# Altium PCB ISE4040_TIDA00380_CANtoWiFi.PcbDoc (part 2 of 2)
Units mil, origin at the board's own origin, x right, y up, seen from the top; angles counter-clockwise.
Board outline 2700 x 3450 mil, 4 copper layers (Top Layer, Signal Layer 1, Signal Layer 2, Bottom Layer), stack 61.6 mil thick; 119 components, 58 nets, 367 pads, 332 vias.
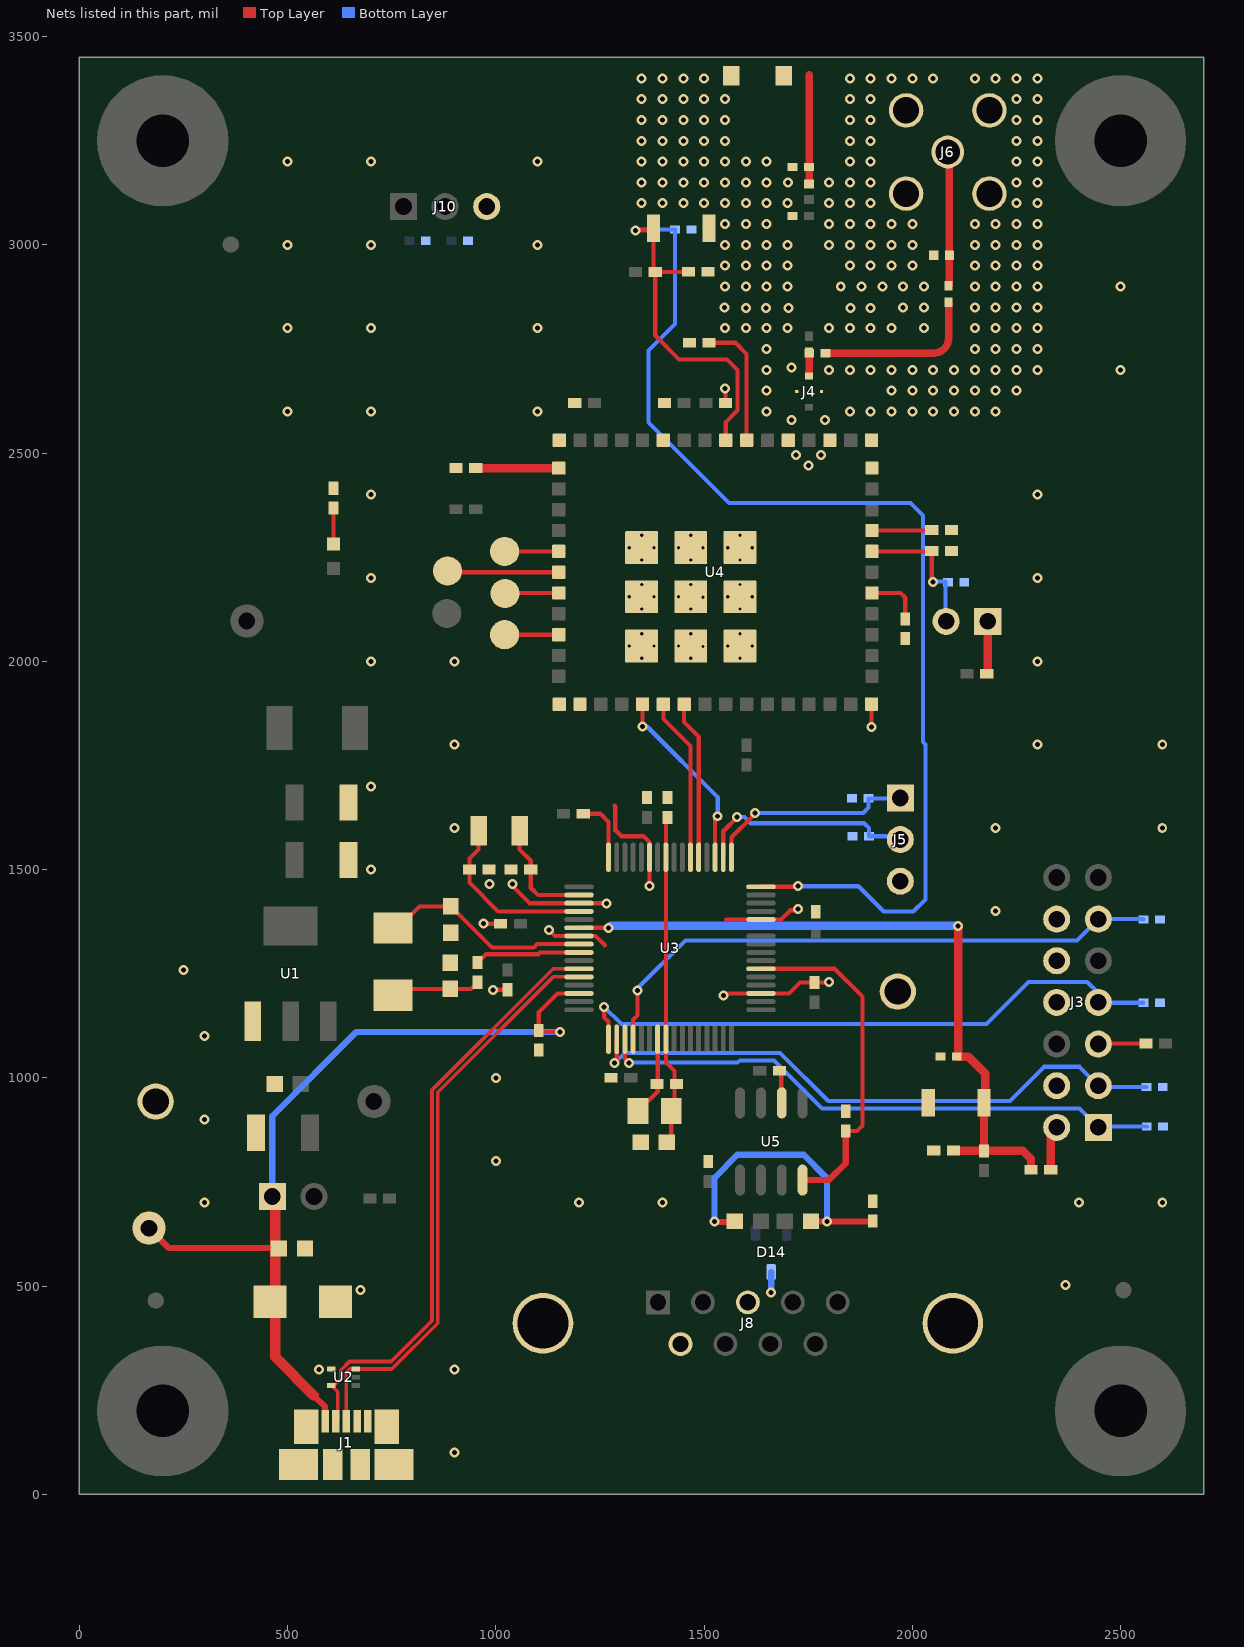
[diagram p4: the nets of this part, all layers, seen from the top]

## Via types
v1: diameter 24, hole 12, Top Layer to Bottom Layer, tented both sides, 294 vias
v2: diameter 19.68, hole 7.87, Top Layer to Bottom Layer, tented both sides, 36 vias
v3: diameter 34, hole 16, Top Layer to Bottom Layer, tented both sides, 2 vias

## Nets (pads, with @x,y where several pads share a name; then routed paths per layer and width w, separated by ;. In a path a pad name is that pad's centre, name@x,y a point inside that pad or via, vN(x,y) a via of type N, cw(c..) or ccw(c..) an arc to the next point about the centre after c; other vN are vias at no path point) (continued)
GND: C1.2 C2.2 C3.2 C4.2 C5.2 C6.2 C7.2 C8.2 C9.2 C10.2 C11.2 C12.2 C13.2 C14.2 C15.2 C18.1 C18.2 C19.2 C20.2 C21.1 C22.1 C23.2 C33.2 C34.2 C35.2 C36.2 C38.2 C39.2 C40.2 C41.2 C42.2 D1.2 D4.2 D6.2 D7.2 D8.2 D9.2 D10.2 D11.2 D12.2 D13.2 D14.3 D15.2 D16.2 E1.1 E1.2 J1.5 J1.6 J1.7 J1.8 J1.9 J1.10 J1.11 J3.4 J3.8 J3.10 J3.12 J4.3 J4.4 J5.3 J6.2 J6.3 J6.4 J6.5 J8.3 J8.6 J8.10 J8.11 J10.3 L3.1 L4.2 R21.1 R23.1 R25.1 R26.1 R27.1 R29.1 R30.1 S1.2 S2.2 TP4.1 TP5.1 U1.1 U2.4 U3.3 U3.12 U3.27 U3.35 U3.39 U3.55 U4.1 U4.2 U4.16 U4.27 U4.28 U4.30 U4.32 U4.38 U4.43 U4.55 U4.56 U4.57 U4.58 U4.59 U4.60 U4.61 U4.62 U4.63 U5.2 | length 1856.2
  Top Layer w10: U2.4@604.47,300.68 U2.4@605.68,300.68 ; v1(970,1370) C6.2@1011.38,1370 ; v1(993,1211) 993.38,1211.38 C7.2@1028,1211.38 ; v1(1040,1465) 1040,1460.22 1080.95,1419.27 U3.35@1199.5,1419.27 v1@1265.73,1419.27 ; v1(1127,1355) 1141.47,1340.53 U3.39@1199.5,1340.53 1239.11,1340.53 1261.43,1318.21 ; 1284.63,1653.53 1286.72,1651.44 1286.72,1594.33 1300.88,1580.17 1354.52,1580.17 1368.79,1565.9 U3.27@1368.79,1529.5 v1@1368.79,1461.21 ; C14.2@1341,920 1388.47,967.47 U3.55@1388.47,1092.5 ; v1(1547,1198) 1551.73,1202.73 U3.3@1636.5,1202.73 1704,1202.73 1729.89,1228.62 C9.2@1765,1228.62 1798.62,1228.62 v1(1800,1230) ; v1(1550,2655) 1551.62,2653.38 C39.2@1551.62,2620 ; 1553.22,1380.42 1553.74,1379.9 U3.12@1636.5,1379.9 1684.95,1379.9 1707.34,1402.29 1725,1402.29 v1(1725,1405) ; C35.2@1680.62,1017 1685,1012.62 1685,940.87 U5.2@1686.35,939.52 ; v1(1902,1842) U4.16@1902,1897.07
  Top Layer w18: L4.2@1752,3146 1752,3408
  Bottom Layer w15: v1@1661,486 D14.3@1661,533.76
  other v1: 900,100 575,300 900,300 1660,485 675,490 2368,502.12 300,700 1200,700 1400,700 2400,700 2600,700 1000,800 300,900 1000,1000 300,1100 249.3,1258.8 2200,1400 1265,1419 1368.79,1460.21 985,1465 700,1500 900,1600 2200,1600 2600,1600 700,1700 900,1800 2300,1800 2600,1800 700,2000 900,2000 2300,2000 700,2200 2300,2200 700,2400 2300,2400 1750,2470 1720,2495 1780,2495 1710,2580 1790,2580 500,2600 700,2600 1100,2600 1650,2600 1850,2600 1900,2600 1950,2600 2000,2600 2050,2600 2100,2600 2150,2600 2200,2600 1650,2650 1950,2650 2000,2650 2050,2650 2100,2650 2150,2650 2200,2650 2250,2650 1650,2700 1800,2700 1850,2700 1900,2700 1950,2700 2000,2700 2050,2700 2100,2700 2150,2700 2200,2700 2250,2700 2300,2700 2500,2700 1710,2705 1650,2750 2150,2750 2200,2750 2250,2750 2300,2750 500,2800 700,2800 1100,2800 1550,2800 1600,2800 1650,2800 1700,2800 1800,2800 1850,2800 1900,2800 1950,2800 2028,2800 2150,2800 2200,2800 2250,2800 2300,2800 1702,2848 1600,2849 1649,2849 1851,2849 1900,2849 1549,2850 1978,2850 2028,2850 2150,2850 2200,2850 2250,2850 2300,2850 1550,2900 1600,2900 1650,2900 1700,2900 1828,2900 1878,2900 1928,2900 1978,2900 2028,2900 2150,2900 2200,2900 2250,2900 2300,2900 2500,2900 1550,2950 1600,2950 1650,2950 1700,2950 1850,2950 1900,2950 1950,2950 2000,2950 2150,2950 2200,2950 2250,2950 2300,2950 500,3000 700,3000 1100,3000 1550,3000 1600,3000 1650,3000 1700,3000 1800,3000 1850,3000 1900,3000 1950,3000 2000,3000 2150,3000 2200,3000 2250,3000 2300,3000 1550,3050 1600,3050 1650,3050 1800,3050 1850,3050 1900,3050 1950,3050 2000,3050 2150,3050 2200,3050 2250,3050 2300,3050 1350,3100 1400,3100 1450,3100 1500,3100 1550,3100 1600,3100 1650,3100 1700,3100 1800,3100 1850,3100 1900,3100 2250,3100 2300,3100 1350,3150 1400,3150 1450,3150 1500,3150 1550,3150 1600,3150 1650,3150 1701,3150 1800,3150 1850,3150 1900,3150 2250,3150 2300,3150 500,3200 700,3200 1100,3200 1350,3200 1400,3200 1450,3200 1500,3200 1550,3200 1600,3200 1650,3200 1850,3200 1900,3200 2250,3200 2300,3200 1350,3250 1400,3250 1450,3250 1500,3250 1550,3250 1850,3250 1900,3250 2250,3250 2300,3250 1350,3300 1400,3300 1450,3300 1500,3300 1550,3300 1850,3300 1900,3300 2250,3300 2300,3300 1350,3350 1400,3350 1450,3350 1500,3350 1550,3350 1850,3350 1900,3350 2250,3350 2300,3350 1350,3400 1400,3400 1450,3400 1500,3400 1850,3400 1900,3400 1950,3400 2000,3400 2050,3400 2150,3400 2200,3400 2250,3400 2300,3400
  other v2: 1349.83,2007.31 1467.94,2007.31 1586.06,2007.31 1497.47,2035.85 1320.31,2036.83 1379.36,2036.83 1438.42,2036.83 1556.53,2036.83 1615.58,2036.83 1349.83,2066.36 1467.94,2066.36 1586.06,2066.36 1349.83,2125.42 1467.94,2125.42 1586.06,2125.42 1497.47,2153.96 1320.31,2154.94 1379.36,2154.94 1438.42,2154.94 1556.53,2154.94 1615.58,2154.94 1349.83,2184.47 1467.94,2184.47 1586.06,2184.47 1349.83,2243.53 1467.94,2243.53 1586.06,2243.53 1320.31,2273.06 1379.36,2273.06 1438.42,2273.06 1497.47,2273.06 1556.53,2273.06 1615.58,2273.06 1349.83,2302.58 1467.94,2302.58 1586.06,2302.58
ID: J1.4
MOSI_CC: U3.22 U4.6 | length 394.6
  Top Layer w10: U4.6@1402,1897.07 1402,1862 1467.21,1796.79 U3.22@1467.21,1529.5
NetC21_2: C21.2 U3.34 Y1.1 | length 270.9
  Top Layer w10: Y1.1@1056.86,1593.15 1056.86,1548.14 1083.62,1521.38 C21.2@1083.62,1500 1083.62,1456.38 1101.05,1438.95 U3.34@1199.5,1438.95
NetC22_2: C22.2 U3.36 Y1.2 | length 425.4
  Top Layer w10: Y1.2@958.44,1593.15 958.44,1548.44 936.38,1526.38 C22.2@936.38,1500 936.38,1468.62 1005.42,1399.58 U3.36@1199.5,1399.58
NetC34_1: C34.1 R17.1 Y2.1 | length 215.9
  Top Layer w10: Y2.1@753,1198.29 768.21,1213.5 C34.1@890,1213.5 940.13,1213.5 R17.1@956,1229.38
NetC41_1: C41.1 R18.1 R19.1 | length 721.5
  Top Layer w15: v1@1526,654 R19.1@1571.5,654 ; R18.1@1754.5,655 v1(1795,655) 1903.62,655 C41.1@1905,656.38
  Bottom Layer w15: v1(1525,655) 1525,760 1580,815 1738.96,815 1795,758.96 v1(1795,655)
NetD5_2: D5.2 R21.2 | length 86.9
  Top Layer w10: D5.2@609.68,2281.53 R21.2@609.68,2368.38
NetJ3_5: J3.5 R14.1 | length 114.8
  Top Layer w10: J3.5@2446.5,1081 2447.5,1082 R14.1@2560.88,1082
NetJ11_1: J11.1 R28.1 | length 127
  Top Layer w20: R28.1@2178.62,1970 2181,1972.38 J11.1@2181,2096
NetR16_2: R16.2 U3.32 | length 153.9
  Top Layer w10: R16.2@1209.62,1634 1251,1634 1270.36,1614.64 U3.32@1270.36,1529.5
NetR30_2: R30.2 U4.21 | length 135.7
  Top Layer w10: U4.21@1902.98,2164 1971.62,2164 1983,2152.62 R30.2@1983,2101.62
NetTP7_1: TP7.1 U4.48 | length 130
  Top Layer w10: TP7.1@1021,2264 U4.48@1151.02,2264
NetTP8_1: TP8.1 U4.49 | length 268.3
  Top Layer w10: TP8.1@884,2217 887,2214 U4.49@1151.02,2214
NetTP9_1: TP9.1 U4.50 | length 128
  Top Layer w10: TP9.1@1023,2164 U4.50@1151.02,2164
NetTP10_1: TP10.1 U4.52 | length 130
  Top Layer w10: TP10.1@1021,2064 U4.52@1151.02,2064
NRST_CC: C42.1 D15.1 R22.1 S2.1 U3.16 U4.35 | length 3490.1
  Top Layer w10: v1(1335,3035) 1373.07,3035 S2.1@1378.07,3040 1378.07,2939.55 R22.1@1382.62,2935 ; C42.1@1462.38,2935.5 1461.88,2935 R22.1@1382.62,2935 ; U4.35@1552,2530.93 1552,2574.61 1580.24,2602.86 1580.24,2699.76 1555,2725 1440,2725 1382.62,2782.38 R22.1@1382.62,2935 ; U3.16@1636.5,1458.64 v1@1723.64,1458.64
  Bottom Layer w10: v1(1335,3035) 1340,3035 1342,3037 D15.1@1430.32,3037 1430.32,2810.31 1366.03,2746.03 1366.03,2573.97 1560,2380 1995.13,2380 2025.13,2350 2025.13,1806.77 2031.53,1800.37 2031.53,1428.37 2002.04,1398.88 1931.28,1398.88 1870.16,1460 v1(1725,1460)
NRST_TM4C: C20.1 D4.1 R11.1 R12.1 S1.1 U3.38 | length 1725.4
  Top Layer w10: U3.38@1199.5,1360.21 v1@1274.79,1360.21
  Top Layer w20: C20.1@2098.62,825 2099,824.62 R11.1@2172,824.62 ; v1(2110,1365) 2110,1054.13 D4.1@2106.68,1050.81 2134.19,1050.81 2175,1010 2175,943.07 S1.1@2171.93,940 2171.93,824.69 R11.1@2172,824.62 ; R12.1@2284.88,779 2284.88,805.12 2265.38,824.62 R11.1@2172,824.62
  Bottom Layer w20: v1(1270,1360) 1275,1365 v1(2110,1365)
NRTS: R23.2 U4.44 | length 199.4
  Top Layer w20: R23.2@951.62,2464 U4.44@1151.02,2464
NTRST: J3.2 R12.2 | length 108
  Top Layer w20: R12.2@2332.13,779 2332.13,866.62 J3.2@2346.5,881
OCS1: R17.2 U3.41 | length 253.7
  Top Layer w10: R17.2@956,1276.62 975.94,1296.56 1101.56,1296.56 1106.16,1301.16 U3.41@1199.5,1301.16
OSC0: C33.1 U3.40 Y2.2 | length 512
  Top Layer w10: Y2.2@753,1359.71 764.71,1359.71 816.5,1411.5 C33.1@892,1411.5 990.5,1313 1091,1313 1098.84,1320.84 U3.40@1199.5,1320.84
RF_FL_O: J4.2 R13.1 R15.2 | length 54.9
  Top Layer w10: R13.1@1752,2739.69 R13.1@1752.32,2740
  Top Layer w18: J4.2@1752,2685.2 R13.1@1752,2739.69
S: R29.2 U3.6 U5.8 | length 824.2
  Top Layer w10: U3.6@1636.5,1261.79 1813.21,1261.79 1880,1195 1880,885 1867.38,872.38 R29.2@1840,872.38
  Top Layer w15: U5.8@1736.35,754.48 1799.48,754.48 1840,795 R29.2@1840,872.38
SCLK_CC: U3.19 U4.5 | length 441.7
  Top Layer w10: v1@1352,1844 U4.5@1352,1897.07 ; U3.19@1526.27,1529.5 v1@1526.27,1621.73
  Bottom Layer w10: v1(1352,1843) 1363.36,1843 1532.54,1673.82 v1(1532.54,1628)
SMA_LEG: C17.2 R13.2 | length 402.2
  Top Layer w18: R13.2@1791.69,2740 2051.17,2740 ccw(c2051.17,2775.83) 2087,2775.83 C17.2@2087,2862.31
SMA_OUT: C17.1 J6.1 L3.2 | length 323.6
  Top Layer w10: J6.1@2085,3223 J6.1@2088.7,3219.3 ; L3.2@2088.7,2975 L3.2@2088.7,2978.3
  Top Layer w18: C17.1@2087,2901.69 2088.7,2903.39 L3.2@2088.7,2975 ; L3.2@2088.7,2978.3 J6.1@2088.7,3219.3
SOMI_CC: U3.21 U4.7 | length 382
  Top Layer w10: U4.7@1452,1897.07 1452,1854 1486.9,1819.1 U3.21@1486.9,1529.5
SOP0: R25.2 U4.34 | length 308.6
  Top Layer w10: R25.2@1511.62,2765 1575,2765 1602,2738 U4.34@1602,2530.93
SOP1: R26.2 U4.24 | length 143.8
  Top Layer w10: U4.24@1902.98,2314 2045.38,2314 R26.2@2046.38,2315
SOP2: D16.1 J11.2 R27.2 U4.23 | length 348.3
  Top Layer w10: U4.23@1902.98,2264 2045.38,2264 R27.2@2046.38,2265 2046.38,2193.62 v1(2050,2190)
  Bottom Layer w10: v1@2048,2192 2079.32,2192 2079.32,2097.68 J11.2@2081,2096
TCK: D13.1 J3.11 U3.52 | length 1411.4
  Top Layer w10: U3.52@1329.42,1092.5 1329.42,1139.42 1340,1150 v1(1340,1210)
  Bottom Layer w10: v1(1340,1210) 1340,1215 1455,1330 2395.51,1330 J3.11@2446.5,1381 2554.32,1381 D13.1@2555.32,1380
TDI: D11.1 J3.3 U3.50 | length 1448.8
  Top Layer w10: v1(1285,1035) 1290.05,1040.05 U3.50@1290.05,1092.5
  Bottom Layer w10: v1(1285,1035) 1285,1035.18 1309.7,1059.87 1682.35,1059.87 1798,944.22 2234.22,944.22 2316.35,1026.35 2401.15,1026.35 J3.3@2446.5,981 2449.5,978 D11.1@2561.82,978
TDO: D10.1 J3.7 U3.49 | length 1465
  Top Layer w10: v1@1260,1165 1260,1145 1270.36,1134.64 U3.49@1270.36,1092.5
  Bottom Layer w10: v1(1260,1170) 1301.23,1128.77 2177.7,1128.77 2278.93,1230 2420,1230 2446.5,1203.5 J3.7@2446.5,1181 2447.5,1180 D10.1@2555.32,1180
TM4C_RX: D7.1 J5.2 U3.18 | length 536.3
  Top Layer w10: U3.18@1545.95,1529.5 1545.95,1591.95 v1@1580,1626
  Bottom Layer w10: v1(1579,1626) 1596.82,1626 1611.7,1611.13 1883.87,1611.13 1895.68,1599.32 D7.1@1895.68,1580 1963,1580 J5.2@1971,1572
TM4C_TX: D6.1 J5.1 U3.17 | length 510.6
  Top Layer w10: U3.17@1565.64,1529.5 1565.64,1577.64 1589.13,1601.13 1589.3,1601.13 1603.87,1615.7 1603.87,1615.87 v1@1626,1638
  Bottom Layer w10: v1(1622,1636) 1882,1636 1894.68,1648.68 D6.1@1894.68,1671 1970,1671 J5.1@1971,1672
TMS: D12.1 J3.1 U3.51 | length 1374.9
  Top Layer w10: U3.51@1309.73,1092.5 1309.73,1045.27 v1(1320,1035)
  Bottom Layer w10: v1(1320,1035) 1321.35,1036.35 1580.17,1036.35 1585.7,1041.87 1667.48,1041.87 1783,926.35 2401.15,926.35 J3.1@2446.5,881 2448.5,883 D12.1@2562.82,883
USB_D_N: J1.2 U2.5 U3.43 | length 1440
  Top Layer w8.5: J1.2@615.41,175.61 620.02,180.22 620.02,245.77 U2.5@604.47,261.31 611.31,261.31 627.5,277.5 627.5,297.84 648.37,318.71 748.71,318.71 846.5,416.5 846.5,970.59 1137.7,1261.79 U3.43@1199.5,1261.79
USB_D_P: J1.3 U2.3 U3.44 | length 1393.2
  Top Layer w8.5: J1.3@641,175.61 641,292.25 649.44,300.68 U2.3@663.53,300.68 749.78,300.68 860,410.91 860,965 1137.1,1242.1 U3.44@1199.5,1242.1
VBUS: C1.1 C23.1 D1.1 J1.1 J2.1 TP1.1 U3.46 | length 2132.1
  Top Layer w10: v1(1154.22,1110) 1099.38,1110 C23.1@1103,1113.62 1103,1158 1147.73,1202.73 U3.46@1199.5,1202.73
  Top Layer w15: TP1.1@167,639 215,591 C1.1@470,591 ; D1.1@457.26,462 D1.1@470,474.74 ; 563,237 589.82,210.18 J1.1@589.82,175.61
  Top Layer w25: J2.1@463,715 J2.1@470,708 ; J2.1@478.5,699.5 J2.1@470,708 ; 563,237 470,330 470,474.74 470,591 J2.1@470,708
  Bottom Layer w15: J2.1@463,715 463,908 665,1110 v1(1154.22,1110)
VDDC_TM4C: C12.1 C13.1 C14.1 C15.1 U3.25 U3.56 | length 798
  Top Layer w10: C15.1@1410.5,845 1421,855.5 C14.1@1421,920 1428.62,927.62 1428.62,1016.38 1408.16,1036.84 U3.56@1408.16,1092.5 U3.25@1408.16,1529.5 1408.16,1621.54 C12.1@1412,1625.38
pads on no net: FID1.1 FID2.1 FID3.1 H1.1 H2.1 H3.1 H4.1 J3.6 J3.9 J3.13 J3.14 J8.1 J8.4 J8.5 J8.8 J8.9 SH-J2.0 SH-J11.0 U2.1 U2.2 U3.1 U3.4 U3.5 U3.7 U3.8 U3.9 U3.10 U3.13 U3.14 U3.15 U3.28 U3.29 U3.30 U3.31 U3.33 U3.45 U3.47 U3.48 U3.53 U3.57 U3.58 U3.61 U3.62 U3.63 U3.64 U4.3 U4.9 U4.12 U4.13 U4.14 U4.15 U4.17 U4.18 U4.19 U4.20 U4.22 U4.25 U4.26 U4.29 U4.33 U4.39 U4.41 U4.42 U4.45 U4.53 U4.54

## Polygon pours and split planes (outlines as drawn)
GND on Signal Layer 1 "Signal Layer 1-No Net" (solid, remove dead copper, pour order 2): 10,3440 10,10 2690,10 2690,3440
GND on Top Layer "Top Layer-No Net" (solid, remove dead copper, pour order 6): 10,3440 10,10 2690,10 2690,3440
GND on Bottom Layer "Bottom Layer-No Net" (solid, remove dead copper, pour order 8): 10,3440 10,10 2690,10 2690,3440
3V3 on Signal Layer 2 "Signal Layer 2-No Net" (solid, remove dead copper, pour order 4): 10,3440 10,10 2690,10 2690,3440

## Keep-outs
Keep-Out Layer:
  lines w10: -5,3450 cw(c0,3450) 0,3455 ; 2600,3455 2700,3455 cw(c2700,3450) 2705,3450 2705,0 cw(c2700,0) 2700,-5 0,-5 cw(c0,0) -5,0 -5,3455 2610,3455
  text ".Layer_Name" at 577,-858.49 h60

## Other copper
Top Layer:
  rectangle net 3V3: 638,1787 782.77,1894
  pour cut-out: 610.8,1913.15 550,1913.15 550,1766 624,1766 624,1899.95
  region net 3V3_OUT: 573,1418 538,1418 538,2161 30,2161 30,1317 573,1317
  pour cut-out: 980,1235 980,1225 1085,1225 1085,1235
  pour cut-out: 1525,1870 1525,1855 1585,1855 1585,1870
  pour cut-out: 1052.87,1473.19 1052.87,1425.79 1085,1425.79 1085,1475 1083.19,1473.19
  pour cut-out: 950,1435 915,1435 915,1473.19 950,1473.19
  pour cut-out: 550,1205 530,1205 530,1195 550,1195
  pour cut-out: 485,1069.8 485,1032.8 501.66,1032.8 501.66,1069.8
  region net 5V: 565,1205 565,1085 505,1025 505,665 720,665 720,830 775,885 775,1006 645,1136 645,1205
  region net GND: 1665,3430 1665,3380 1850,3380 1850,3430
  pour cut-out: 1780,2555 1780,3250 1724,3250 1724,2555
  text ".Layer_Name" at 577,-858.49 h60
Signal Layer 2:
  pour cut-out: 2340,2440 1540,2440 1540,3450 2335,3450 2340,3455
Bottom Layer:
  text ".Layer_Name" at 577,-858.49 h60
Multi-Layer:
  pour cut-out: 1801,3452 1564.25,3452 1564.25,3235 1801,3235

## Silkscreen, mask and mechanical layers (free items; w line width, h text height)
Top Overlay:
  text "HEADER" at 979.59,3327 h50 r180
  text "PROGRAMMING" at 1059,3287 h50 r180
  text "CC3100MOD" at 1018.92,3248 h50 r180
  text "TX" at 805.58,3203.06 h60 r180
  text "RX" at 907.53,3203.06 h60 r180
  text "GND" at 1037,3202 h60 r180
  text "TI" at 415,2686 h105 r90
  text ".TID" at 160,2520 h105 r90
  text ".CopyrightYear" at 415,2410 h105 r90
  text ".PCB_Rev" at 160,2340 h105 r90
  text "©" at 425,2300 h105 r90
  text "+3.3V" at 324,1983 h60
  text ".PRJ_Number" at 160,1740 h105 r90
  text "TX" at 2088,1639 h60 r90
  text "RX" at 2088,1540 h60 r90
  text "HEADER" at 2190,1463.41 h50 r90
  text "GND" at 2088,1400 h60 r90
  text "TM4C CONSOLE UART" at 2144,1329 h50 r90
  text "GND" at 1905,1080 h60
  text "JTAG" at 2256,1028 h100 r90
  text "+5V" at 660,835 h60
  text "GND" at 127,815 h60
  text "VBUS" at 96,533 h60
  text ".Layer_Name" at 577,-858.49 h60
Bottom Overlay:
  text ".Layer_Name" at 577,-858.49 h60
Top Paste:
  text ".Layer_Name" at 577,-858.49 h60
Bottom Paste:
  text ".Layer_Name" at 577,-858.49 h60
Top Solder:
  text ".Layer_Name" at 577,-858.49 h60
  text ".Layer_Name" at 577,-858.49 h60
Bottom Solder:
  text ".Layer_Name" at 577,-858.49 h60
Drill Guide:
  text ".Layer_Name" at 577,-858.49 h60
M1 Board Outline:
  the board outline again, w10
  text ".Layer_Name" at 577,-858.49 h60
M2 Board Dimensions:
  rectangle: 0,-275 125,-150
  rectangle: 125,-400 500,-275
  lines w7: 0,-275 1000,-275 ; 125,-400 125,-150 ; 250,-400 250,-150 ; 500,-400 500,-150 ; 750,-400 750,-150 ; 0,-400 1000,-400 1000,-150 0,-150 0,-400
  text ".Layer_Name" at 577,-858.49 h60
M3 3D STEP Top:
  text ".Layer_Name" at 577,-858.49 h60
M4 3D STEP Bottom:
  text ".Layer_Name" at 577,-858.49 h60
M5 Assembly Top:
  lines w10: -292,-930.17 6308,-930.17 ; -292,-726.83 6310,-726.83 ; -292,-523.5 -292,-1133.5 3713,-1133.5 6310,-1133.5 6310,-523.5 -291.5,-523.5 -291.5,-1133.5 1284,-1133.5 ; 2173,-1133.5 2173,-523.5 ; 3440,-726.83 3440,-523.5 ; 4280,-726.83 4280,-523.5 ; 4902,-1140 4902,-937.17
  text "COMPONENTS MARKED 'DNP' SHOULD NOT BE POPULATED." at 1153.5,-318.5 h60
  text "ASSEMBLY VARIANT:" at 1153,-434 h60
  text ".VariantName" at 2189,-434 h60
  text "PCB VIEWED FROM TOP SIDE" at -228.5,-655.67 h60
  text "BOARD #:" at 2248,-655.67 h60
  text ".PRJ_Number" at 2793.5,-655.67 h60
  text "REV:" at 3638,-655.67 h60
  text ".PCB_Rev" at 3929.5,-655.67 h60
  text "SVN REV:" at 4476,-655.67 h60
  text ".VersionControl_RevNumber" at 4982,-655.67 h60
  text "TID #:" at 2220,-870 h60
  text ".TID" at 2765.5,-870 h60
  text "PLOT NAME =" at -228.5,-1064.34 h60
  text ".plot_File_Name" at 577,-1064.34 h60
  text "GENERATED    :" at 2250,-1064.34 h60
  text ".Print_Date" at 3119.5,-1064.34 h60
  text ".Print_Time" at 3848.5,-1064.34 h60
  text "TEXAS INSTRUMENTS" at 5113,-1064.34 h60
M6 Assembly Bottom:
  lines w10: -292.5,-727.33 6309.5,-727.33 ; -290.5,-930.67 6309.5,-930.67 ; 1115.5,-1140.5 1115.5,-937.67 ; 1737.5,-727.33 1737.5,-524 ; 2577.5,-727.33 2577.5,-524 ; 3844.5,-1134 3844.5,-524 ; 4733.5,-1134 6309,-1134 6309,-524 -292.5,-524 -292.5,-1134 2304.5,-1134 6309.5,-1134 6309.5,-524
  text "COMPONENTS MARKED 'DNP' SHOULD NOT BE POPULATED." at 6102,-318 h60
  text ".VariantName" at 5058,-434 h60
  text "ASSEMBLY VARIANT:" at 6097,-434 h60
  text ".VersionControl_RevNumber" at 1035.5,-656.17 h60
  text "SVN REV:" at 1541.5,-656.17 h60
  text ".PCB_Rev" at 2088,-656.17 h60
  text "REV:" at 2379.5,-656.17 h60
  text ".PRJ_Number" at 3224,-656.17 h60
  text "BOARD #:" at 3769.5,-656.17 h60
  text "PCB VIEWED FROM BOTTOM SIDE" at 6246,-656.17 h60
  text ".TID" at 3196,-870.5 h60
  text "TID #:" at 3741.5,-870.5 h60
  text "TEXAS INSTRUMENTS" at 904.5,-1064.84 h60
  text ".Print_Time" at 2169,-1064.84 h60
  text ".Print_Date" at 2898,-1064.84 h60
  text "GENERATED    :" at 3767.5,-1064.84 h60
  text ".plot_File_Name" at 5440.5,-1064.84 h60
  text "PLOT NAME =" at 6246,-1064.84 h60
M9 Title Sheet:
  drawing of 57 lines, arcs and shapes, not listed
  text "1" at 739.84,8036.5 h70
  text "2" at 3235.5,8036.5 h70
  text "3" at 5724.84,8036.5 h70
  text "4" at 8231.51,8036.5 h70
  text "5" at 10730.5,8036.5 h70
  text "6" at 13235.5,8036.5 h70
  text "A" at -416.5,6893.5 h70
  text "A" at 14383.5,6893.5 h70
  text "B" at -416.5,4513.5 h70
  text "B" at 14383.5,4513.5 h70
  text "C" at -416.5,2138.5 h70
  text "C" at 14383.5,2138.5 h70
  text "PROJECT TITLE:" at 11343.5,277.5 h45
  text ".PRJ_Title" at 11393.5,144.17 h70
  text "DESIGNED FOR:" at 11343.5,-23.5 h45
  text ".PRJ_Customer" at 11393.5,-163.5 h70
  text "D" at -416.5,-231.5 h70
  text "D" at 14383.5,-231.5 h70
  text "FILE NAME:" at 11343.5,-323.5 h45
  text ".PCB_File_Name_No_Path" at 11393.5,-443.5 h70
  text "Texas Instruments (TI) and/or its licensors do not warrant the accuracy or completeness of this specification" at 6374,-605.34 h45
  text "ENGINEER:" at 11343.5,-613.5 h45
  text "LAYOUT BY:" at 12848.5,-613.5 h45
  text "or any information contained therein. TI and/or its licensors do not warrant that this design will meet" at 6329.01,-718 h45
  text ".PRJ_Engineer" at 11393.5,-768.49 h70
  text ".PCB_Layout" at 12899,-768.49 h70
  text "the specifications, will be suitable for your application or fit for any particular purpose, or will operate in" at 6329.01,-830.67 h45
  text ".Layer_Name" at 577,-858.49 h60
  text "ALTIUM DESIGNER VERSION:" at 12848.5,-923.5 h45
  text "an implementation. TI and/or its licensors do not warrant that the design is production worthy. You should" at 6329.01,-943.33 h45
  text "completely validate and test your design implementation to confirm the system functionality for your application." at 6374,-1056 h45
  text ".print_Scale" at 11393.5,-1056.83 h70
  text ".Application_BuildNumber" at 12899,-1056.83 h70
  text "1" at 739.84,-1263.5 h70
  text "2" at 3235.5,-1263.5 h70
  text "3" at 5724.84,-1263.5 h70
  text "4" at 8231.51,-1263.5 h70
  text "5" at 10730.5,-1263.5 h70
  text "6" at 13235.5,-1263.5 h70
M10 Fab Notes:
  drawing of 185 lines, arcs and shapes, not listed
  text "FABRICATION NOTES" at -109.99,7033.82 h150
  text "1. Top Layer contains 90 ohm differential using 8.5 mil trace and 5 mil spacing." at -110,6850 h150
  text "2. Top Layer contains 50 ohm controlled impedance using 18 mil trace." at -114.97,6686.06 h150
  text "DESIGN INFORMATION" at 12381.02,5910 h60
  text "MIN. TRACK WIDTH:" at 11736.46,5730 h60
  text "MIL" at 12987.46,5730 h60
  text "8.5" at 12772,5727 h60
  text "MIN. CLEARANCE:" at 11736.46,5598 h60
  text "0.2" at 12772.7,5598 h60
  text "mm" at 12987.46,5598 h60
  text "MIN. VIA PAD SIZE:" at 11736.46,5466 h60
  text "24" at 12802.71,5466 h60
  text "MIL" at 12987.46,5466 h60
  text "0.05mm (2MIL)" at 12431.46,5324.29 h60
  text "MINIMUM ANNULAR RING" at 11407.23,5320 h60
  text "EXTERNAL" at 13139.46,5320 h60
  text "PER" at 11607.23,5202 h60
  text "IPC-D-275 CLASS 2 LEVEL C" at 11827.23,5202 h60
  text "MIL, HOLES" at 13315.46,5089.71 h60
  text "+/-" at 12923,5089 h60
  text "+/-" at 13777,5089 h60
  text "REGISTRATION TOLERANCES:" at 11407.23,5084 h60
  text "METAL" at 12607,5084 h60
  text "5" at 13183.2,5084 h60
  text "3" at 14016.2,5084 h60
  text "MIL" at 14132.46,5084 h60
  text "MATERIAL:" at 11332.46,4874.54 h60
  text "FR-4 High Tg" at 12318.9,4734.21 h60
  text "FR-408" at 11753.46,4725.64 h60
  text "X" at 12165.46,4725.64 h60
  text "OTHER" at 13241.46,4725.64 h60
  text "62 MIL (1.6mm) +/-10%" at 12073.56,4562.92 h60
  text "THICKNESS:" at 11407.23,4558.64 h60
  text "X" at 11945.4,4558.64 h60
  text "OTHER" at 13358.46,4558.64 h60
  text "TOLERANCE:" at 11407.23,4400.64 h60
  text "X" at 12246.53,4400.64 h60
  text "ANSI IPC-6012 TYPE 3 CLASS 2" at 12433.48,4400.64 h60
  text "OTHER +/-" at 12433.46,4244.64 h60
  text "BOW & TWIST:" at 11407.23,4087.64 h60
  text "X" at 12246.53,4087.64 h60
  text "ANSI IPC-6012 TYPE 3 CLASS 2" at 12433.48,4087.64 h60
  text "OTHER +/-" at 12433.46,3929.13 h60
  text "DRILLING:" at 11332.46,3790.64 h60
  text "REFERENCE:" at 11407.23,3673.64 h60
  text "X" at 12055.46,3673.64 h60
  text "AS SHOWN" at 12242.46,3673.64 h60
  text "X" at 12956.46,3673.64 h60
  text "NC_DRILL FILES" at 13093.46,3673.64 h60
  text "PTH MIN COPPER THICKNESS:" at 11407.23,3515.64 h60
  text "X" at 12757.46,3515.64 h60
  text "1MIL" at 12894.46,3515.64 h60
  text "OTHER" at 13391.46,3515.64 h60
  text "BOARD FINISH:" at 11332.46,3356.64 h60
  text "SILKSCREEN:" at 11487.68,3238.64 h60
  text "X" at 12436.46,3238.64 h60
  text "TOP" at 12562.46,3238.64 h60
  text "X" at 12946.46,3238.64 h60
  text "BOTTOM" at 13073.46,3238.64 h60
  text "SILKSCREEN COLOR:" at 11487.68,3071.64 h60
  text "X" at 12435.42,3071.64 h60
  text "WHITE" at 12562.46,3071.64 h60
  text "OTHER" at 13073.46,3071.64 h60
  text "SOLDER RESIST COLOR:" at 11487.68,2901.64 h60
  text "X" at 12055.42,2742.44 h60
  text "GREEN" at 12182.46,2742.44 h60
  text "BLUE" at 12773.46,2742.44 h60
  text "OTHER" at 13311.46,2742.44 h60
  text "IMMERSION GOLD (ENIG)" at 12393.46,2553.92 h60
  text "ENEPIG" at 13731,2550.64 h60
  text "SURFACE FINISH:" at 11332.46,2549.64 h60
  text "X" at 12206.51,2549.64 h60
  text "IMM. TIN/SILVER OR EQUIV" at 11662,2392.64 h60
  text "OTHER" at 13093.46,2392.64 h60
  text "ARRAY/PANEL:" at 11332.46,2213.64 h60
  text "CUT AND TRIM PER MECH LAYER 1" at 12393.46,2209.35 h60
  text "N.C. ROUTE" at 12393.46,2057.64 h60
  text "X" at 13072.46,2057.64 h60
  text "V. SCORE" at 13259.46,2057.64 h60
  text "CERTIFICATION:" at 11332.46,1920.64 h60
  text "MATERIALS AND WORKMANSHIP FOR ALL PCBS" at 12057.46,1920.64 h60
  text "TO MEET OR EXCEED THE REQUIREMENTS OF:" at 12057.46,1822.64 h60
  text "X" at 11683.96,1686.13 h60
  text "ANSI IPC-A-600F CLASS ->" at 11822.96,1686.13 h60
  text "X" at 13462.02,1686.13 h60
  text "2" at 13580.96,1686.14 h60
  text "1" at 13265.96,1684.64 h60
  text "3" at 13934.96,1684.64 h60
  text "X" at 11686.02,1526.64 h60
  text "UL 94V-0" at 11822.96,1526.64 h60
  text "X" at 12498.02,1526.64 h60
  text "RoHS" at 12634.96,1526.64 h60
  text "OTHER" at 13279.36,1526.64 h60
  text "PER ORDER" at 13676.42,1526.64 h60
  text "ADDITIONAL REQUIREMENTS:" at 11332.46,1385.64 h60
  text "MICROSECTION:" at 11407.23,1270.64 h60
  text "YES" at 12312.96,1270.64 h60
  text "REQUIRED" at 13174.46,1114.49 h60
  text "BARE BOARD ELEC. TEST:" at 11407.23,1111.64 h60
  text "NONE" at 12712.96,1111.64 h60
  text "X" at 13047.46,1111.64 h60
  text "PER ORDER" at 13766.46,1111.64 h60
  text "MANUFACTURER'S UL:" at 11407.23,954.64 h60
  text "RAIL" at 12572.96,950.35 h60
  text "METAL" at 13064.77,950.35 h60
  text "X" at 13440,950 h60
  text "SILK" at 13576.46,950.35 h60
  text ".Layer_Name" at 577,-858.49 h60
M11 Gerber Information:
  lines w10: -292,-930.17 6308,-930.17 ; -292,-726.83 6310,-726.83 ; -292,-523.5 -292,-1133.5 3713,-1133.5 6310,-1133.5 6310,-523.5 -291.5,-523.5 -291.5,-1133.5 1284,-1133.5 ; 2173,-1133.5 2173,-523.5 ; 3440,-726.83 3440,-523.5 ; 4280,-726.83 4280,-523.5 ; 4902,-1140 4902,-937.17
  text "ALL ARTWORK VIEWED FROM TOP SIDE" at -228.5,-655.67 h60
  text "BOARD #:" at 2248,-655.67 h60
  text ".PRJ_Number" at 2793.5,-655.67 h60
  text "REV:" at 3638,-655.67 h60
  text ".PCB_Rev" at 3929.5,-655.67 h60
  text "SVN REV:" at 4476,-655.67 h60
  text ".VersionControl_RevNumber" at 4982,-655.67 h60
  text "LAYER NAME =" at -228.5,-858.49 h60
  text "TID #:" at 2220,-870 h60
  text ".TID" at 2765.5,-870 h60
  text "PLOT NAME =" at -228.5,-1064.34 h60
  text ".plot_File_Name" at 577,-1064.34 h60
  text "GENERATED    :" at 2250,-1064.34 h60
  text ".Print_Date" at 3119.5,-1064.34 h60
  text ".Print_Time" at 3848.5,-1064.34 h60
  text "TEXAS INSTRUMENTS" at 5113,-1064.34 h60
M12 Stackup:
  drawing of 295 lines, arcs and shapes, not listed
  text "Layer" at 9685,7670 h60
  text "Name" at 10094.91,7670 h60
  text "Material" at 11034.65,7670 h60
  text "Thickness" at 11894.42,7670 h60
  text "Constant" at 12544.26,7670 h60
  text "Board Layer Stack" at 13114.12,7670 h60
  text "1" at 9685,7550 h60
  text "Top Overlay" at 10094.91,7550 h60
  text "2" at 9685,7430 h60
  text "Top Solder" at 10094.91,7430 h60
  text "Solder Resist" at 11034.65,7430 h60
  text "0.40mil" at 11894.42,7430 h60
  text "3.5" at 12544.26,7430 h60
  text "3" at 9685,7310 h60
  text "Top Layer" at 10094.91,7310 h60
  text "Copper" at 11034.65,7310 h60
  text "1.40mil" at 11894.42,7310 h60
  text "4" at 9685,7190 h60
  text "Dielectric1" at 10094.91,7190 h60
  text "FR-4 High TG" at 11034.65,7190 h60
  text "10.00mil" at 11894.42,7190 h60
  text "4.2" at 12544.26,7190 h60
  text "5" at 9685,7070 h60
  text "Signal Layer 1" at 10094.91,7070 h60
  text "Copper" at 11034.65,7070 h60
  text "1.40mil" at 11894.42,7070 h60
  text "6" at 9685,6950 h60
  text "Dielectric 3" at 10094.91,6950 h60
  text "FR-4 High TG" at 11034.65,6950 h60
  text "36.00mil" at 11894.42,6950 h60
  text "4.2" at 12544.26,6950 h60
  text "7" at 9685,6830 h60
  text "Signal Layer 2" at 10094.91,6830 h60
  text "Copper" at 11034.65,6830 h60
  text "1.40mil" at 11894.42,6830 h60
  text "8" at 9685,6710 h60
  text "Dielectric 2" at 10094.91,6710 h60
  text "FR-4 High TG" at 11034.65,6710 h60
  text "10.00mil" at 11894.42,6710 h60
  text "4.2" at 12544.26,6710 h60
  text "9" at 9685,6590 h60
  text "Bottom Layer" at 10094.91,6590 h60
  text "Copper" at 11034.65,6590 h60
  text "1.40mil" at 11894.42,6590 h60
  text "10" at 9685,6470 h60
  text "Bottom Solder" at 10094.91,6470 h60
  text "Solder Resist" at 11034.65,6470 h60
  text "0.40mil" at 11894.42,6470 h60
  text "3.5" at 12544.26,6470 h60
  text "11" at 9685,6350 h60
  text "Bottom Overlay" at 10094.91,6350 h60
  text ".Layer_Name" at 577,-858.49 h60
M13 Component Bodies Top:
  text ".Layer_Name" at 577,-858.49 h60
M14 Component Bodies Bottom:
  text ".Layer_Name" at 577,-858.49 h60
M15 Courtyards Top:
  text ".Layer_Name" at 577,-858.49 h60
M16 Courtyards Bottom:
  text ".Layer_Name" at 577,-858.49 h60
Drill Drawing:
  circle w10: c3547.82,2285.77 r24.92
  circle w10: c3547.82,1986.77 r14.95
  circle w10: c3547.82,1986.77 r24.92
  lines w10: 3522.91,915.35 3572.74,915.35 3572.74,965.18 3522.91,965.18 3522.91,915.35 ; 3522.91,1077.31 3535.37,1077.31 3547.82,1064.85 3560.28,1077.31 3572.74,1077.31 3560.28,1089.77 3572.74,1102.22 3560.28,1102.22 3547.82,1114.68 3535.37,1102.22 3522.91,1102.22 3535.37,1089.77 3522.91,1077.31 ; 3522.91,1214.35 3572.74,1214.35 3572.74,1264.18 3522.91,1264.18 3522.91,1214.35 ; 3522.91,1388.77 3547.82,1363.85 3572.74,1388.77 3547.82,1413.68 3522.91,1388.77 ; 3522.91,1513.35 3522.91,1525.81 3535.37,1538.27 3522.91,1550.72 3522.91,1563.18 3535.37,1563.18 3547.82,1550.72 3560.28,1563.18 3572.74,1563.18 3572.74,1550.72 3560.28,1538.27 3572.74,1525.81 3572.74,1513.35 3560.28,1513.35 3547.82,1525.81 3535.37,1513.35 3522.91,1513.35 ; 3522.91,1675.31 3535.37,1675.31 3547.82,1662.85 3560.28,1675.31 3572.74,1675.31 3560.28,1687.77 3572.74,1700.22 3560.28,1700.22 3547.82,1712.68 3535.37,1700.22 3522.91,1700.22 3535.37,1687.77 3522.91,1675.31 ; 3522.91,1862.18 3572.74,1862.18 3547.82,1812.35 3522.91,1862.18 ; 3522.91,2111.35 3547.82,2123.81 3572.74,2111.35 3560.28,2136.27 3572.74,2161.18 3547.82,2148.72 3522.91,2161.18 3535.37,2136.27 3522.91,2111.35 ; 3532.88,1082.29 3540.35,1082.29 3547.82,1074.82 3555.3,1082.29 3562.77,1082.29 3555.3,1089.77 3562.77,1097.24 3555.3,1097.24 3547.82,1104.72 3540.35,1097.24 3532.88,1097.24 3540.35,1089.77 3532.88,1082.29 ; 3532.88,1224.32 3562.77,1224.32 3562.77,1254.22 3532.88,1254.22 3532.88,1224.32 ; 3532.88,1852.22 3562.77,1852.22 3547.82,1822.32 3532.88,1852.22
  lines w12: 3455,870.5 5573.44,870.5 ; 3455,2365.5 5573.44,2365.5 ; 3825.51,721 3825.51,2515 ; 4182.67,721 4182.67,2515 ; 4844.15,721 4844.15,2515 ; 5128.35,721 5128.35,2515 ; 3455,721 5573.44,721 5573.44,2515 3455,2515 3455,721
  text "Symbol" at 3544.7,2410.35 h72
  text "Quantity" at 3870.36,2410.35 h72
  text "Finished Hole Size" at 4227.52,2410.35 h72
  text "Plated" at 4889,2410.35 h72
  text "Hole Type" at 5173.2,2410.35 h72
  text "36" at 3870.36,2260.85 h60
  text "7.87mil (0.200mm)" at 4227.52,2260.85 h60
  text "PTH" at 4889,2260.85 h60
  text "Round" at 5173.2,2260.85 h60
  text "294" at 3870.36,2111.35 h60
  text "12.00mil (0.305mm)" at 4227.52,2111.35 h60
  text "PTH" at 4889,2111.35 h60
  text "Round" at 5173.2,2111.35 h60
  text "2" at 3870.36,1961.85 h60
  text "16.00mil (0.406mm)" at 4227.52,1961.85 h60
  text "PTH" at 4889,1961.85 h60
  text "Round" at 5173.2,1961.85 h60
  text "9" at 3870.36,1812.35 h60
  text "39.37mil (1.000mm)" at 4227.52,1812.35 h60
  text "PTH" at 4889,1812.35 h60
  text "Round" at 5173.2,1812.35 h60
  text "27" at 3870.36,1662.85 h60
  text "40.00mil (1.016mm)" at 4227.52,1662.85 h60
  text "PTH" at 4889,1662.85 h60
  text "Round" at 5173.2,1662.85 h60
  text "1" at 3870.36,1513.35 h60
  text "59.06mil (1.500mm)" at 4227.52,1513.35 h60
  text "PTH" at 4889,1513.35 h60
  text "Round" at 5173.2,1513.35 h60
  text "4" at 3870.36,1363.85 h60
  text "62.99mil (1.600mm)" at 4227.52,1363.85 h60
  text "PTH" at 4889,1363.85 h60
  text "Round" at 5173.2,1363.85 h60
  text "2" at 3870.36,1214.35 h60
  text "63.00mil (1.600mm)" at 4227.52,1214.35 h60
  text "PTH" at 4889,1214.35 h60
  text "Round" at 5173.2,1214.35 h60
  text "2" at 3870.36,1064.85 h60
  text "122.05mil (3.100mm)" at 4227.52,1064.85 h60
  text "PTH" at 4889,1064.85 h60
  text "Round" at 5173.2,1064.85 h60
  text "4" at 3870.36,915.35 h60
  text "125.98mil (3.200mm)" at 4227.52,915.35 h60
  text "PTH" at 4889,915.35 h60
  text "Round" at 5173.2,915.35 h60
  text "381 Total" at 3870.36,765.85 h60
  text ".Layer_Name" at 577,-858.49 h60

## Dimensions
0,0 to 0,3450 on M2 Board Dimensions
0,-400 to 1000,-400 on M2 Board Dimensions
0,0 to 2700,-27 on M2 Board Dimensions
